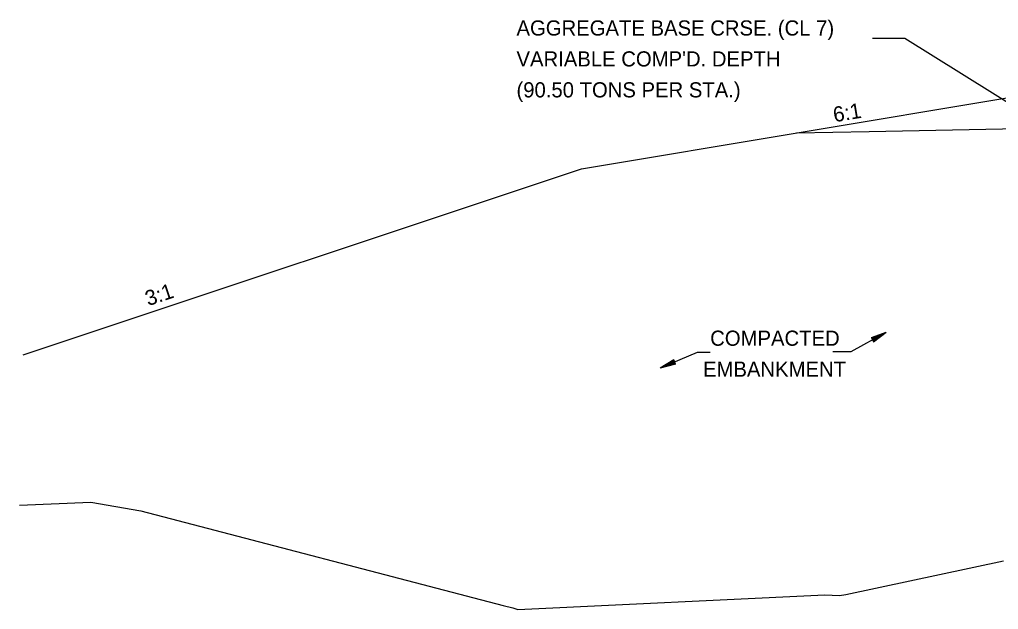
# Model space of a CAD drawing. Extents: x 634177 to 635904, y 289936 to 290970.
# Drawn here: x 635612.03 to 635649.48, y 290383.97 to 290406.55 of the extents above; entities that cross this region are included whole.
import ezdxf

# ---------------------------------------------------------------- set-up
doc = ezdxf.new("R2010")
doc.units = 0
for name, color, linetype in [('1', 7, 'Continuous'), ('7', 7, 'Continuous'), ('Default', 7, 'Continuous'), ('R_Alt Surface', 7, 'Continuous'), ('R_Exist Surface', 7, 'Continuous'), ('R_Xsect Slope', 7, 'Continuous')]:
    doc.layers.add(name, color=color, linetype=linetype)

msp = doc.modelspace()

# ---------------------------------------------------------------- linework, layer by layer
at = {"layer": '1'}
for p, q in [((635644.665, 290405.828), (635645.897, 290405.828)), ((635645.897, 290405.828), (635650.838, 290402.756)), ((635643.847, 290393.842), (635645.188, 290394.583)), ((635637.953, 290393.806), (635636.541, 290393.206)), ((635638.447, 290393.806), (635637.953, 290393.806)), ((635643.141, 290393.842), (635643.847, 290393.842))]:
    msp.add_line(p, q, dxfattribs=at)
at = {"layer": '7'}
for p, q in [((635644.619, 290394.372), (635645.187, 290394.584)), ((635644.619, 290394.372), (635644.706, 290394.215)), ((635644.626, 290394.359), (635645.1, 290394.535)), ((635644.634, 290394.346), (635645.009, 290394.485)), ((635644.641, 290394.332), (635644.922, 290394.437)), ((635644.648, 290394.319), (635644.833, 290394.388)), ((635644.656, 290394.306), (635644.745, 290394.339)), ((635644.669, 290394.281), (635644.745, 290394.339)), ((635644.677, 290394.268), (635644.833, 290394.388)), ((635644.684, 290394.254), (635644.922, 290394.437)), ((635644.691, 290394.241), (635645.009, 290394.485)), ((635644.699, 290394.228), (635645.1, 290394.535)), ((635644.706, 290394.215), (635645.187, 290394.584)), ((635637.058, 290393.524), (635636.541, 290393.206)), ((635637.128, 290393.358), (635637.058, 290393.524)), ((635637.128, 290393.358), (635636.541, 290393.206)), ((635637.064, 290393.51), (635636.633, 290393.246)), ((635637.122, 290393.372), (635636.633, 290393.246)), ((635637.07, 290393.496), (635636.728, 290393.286)), ((635637.116, 290393.386), (635636.728, 290393.286)), ((635637.075, 290393.482), (635636.82, 290393.325)), ((635637.11, 290393.4), (635636.82, 290393.325)), ((635637.081, 290393.468), (635636.913, 290393.365)), ((635637.104, 290393.414), (635636.913, 290393.365)), ((635637.087, 290393.454), (635637.006, 290393.404)), ((635637.098, 290393.428), (635637.006, 290393.404))]:
    msp.add_line(p, q, dxfattribs=at)
at = {"layer": 'Default'}
msp.add_lwpolyline([(635612.168, 290393.713), (635633.533, 290400.834), (635650.033, 290403.585)], dxfattribs=at)
at = {"layer": 'R_Alt Surface'}
for points in [[(635644.53, 290402.261), (635656.03, 290402.491), (635687.53, 290403.121)], [(635641.76, 290402.206), (635644.53, 290402.261)]]:
    msp.add_lwpolyline(points, dxfattribs=at)
at = {"layer": 'R_Exist Surface'}
msp.add_lwpolyline([(635612.029, 290387.967), (635614.762, 290388.079), (635616.665, 290387.744), (635630.537, 290384.125), (635630.903, 290384.032), (635631.095, 290383.97), (635642.842, 290384.527), (635643.405, 290384.507), (635643.646, 290384.545), (635649.676, 290385.827)], dxfattribs=at)

# ---------------------------------------------------------------- texts
at = {"layer": '1'}
for s, p in [('AGGREGATE BASE CRSE. (CL 7)', (635631.042, 290405.934)), ("VARIABLE COMP'D. DEPTH", (635631.042, 290404.75)), ('(90.50 TONS PER STA.)', (635631.042, 290403.566)), ('COMPACTED', (635638.453, 290394.061)), ('EMBANKMENT', (635638.179, 290392.877))]:
    msp.add_text(s, height=0.58, dxfattribs=at).set_placement(p)
at = {"layer": 'R_Xsect Slope'}
for s, rotation, p in [('6:1', 9.4623, (635643.208, 290402.614)), ('3:1', 18.4349, (635616.95, 290395.576))]:
    msp.add_text(s, height=0.58, rotation=rotation, dxfattribs=at).set_placement(p)

doc.saveas('drawing.dxf')
